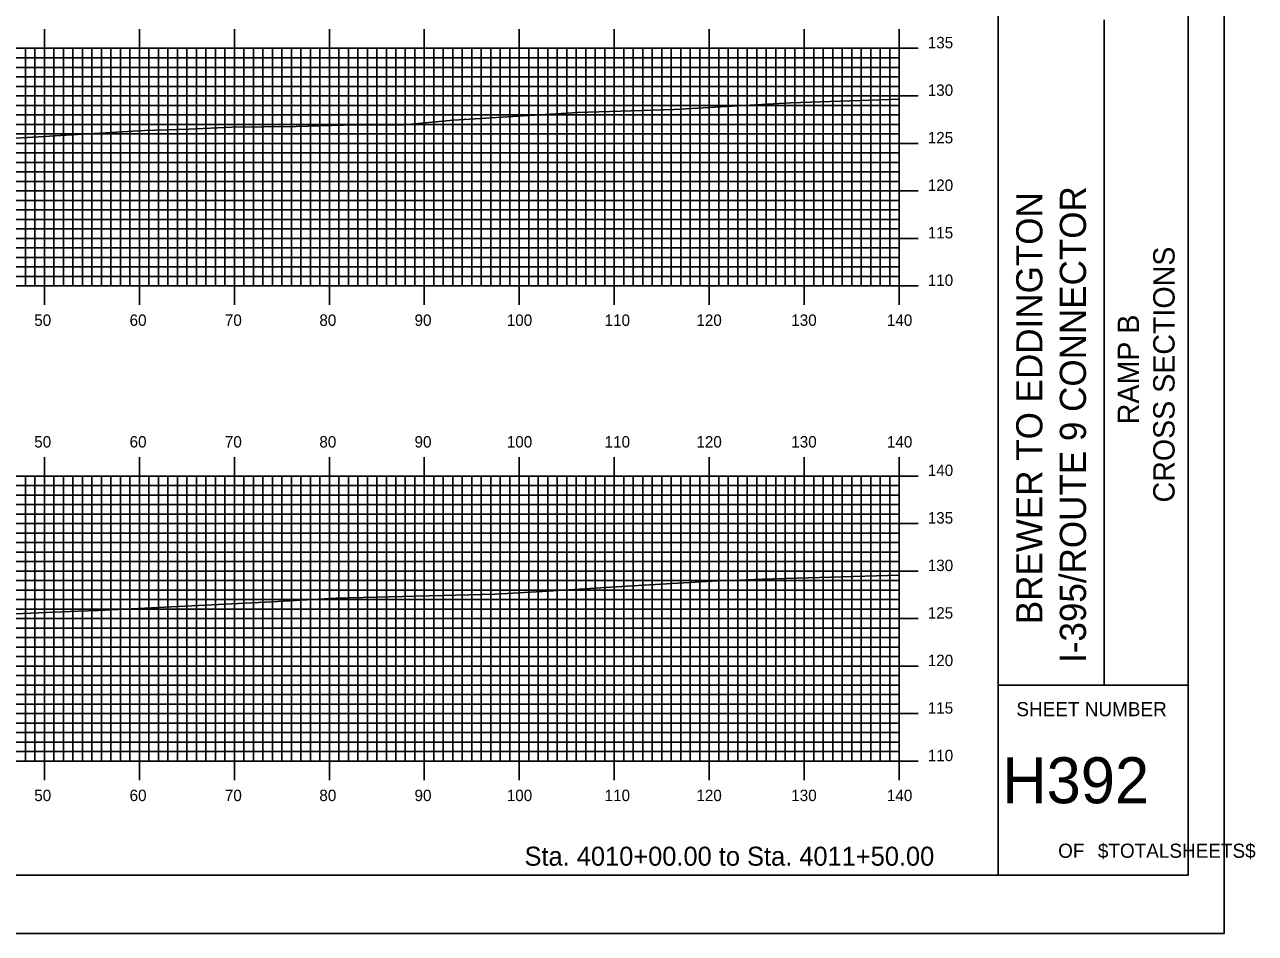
# Model space of a CAD drawing. Extents: x 852540 to 852884, y 364661 to 364881.
# Drawn here: x 852754.2 to 852883.8, y 364661.3 to 364756.9 of the extents above; entities that cross this region are included whole.
import ezdxf

# ---------------------------------------------------------------- set-up
doc = ezdxf.new("R2010")
doc.units = 0
for name, color, linetype in [('BORDER', 7, 'Continuous'), ('H_V ANNOTATION', 7, 'Continuous'), ('MAJOR', 7, 'Continuous'), ('MINOR', 7, 'Continuous'), ('PLOT BOUNDARY', 7, 'Continuous'), ('S_Roadway_Centerline', 7, 'Continuous')]:
    doc.layers.add(name, color=color, linetype=linetype)

msp = doc.modelspace()

# ---------------------------------------------------------------- linework, layer by layer
at = {"layer": 'BORDER'}
for p, q in [((852856.67, 364667.37), (852856.67, 364877.37)), ((852867.85, 364687.38), (852867.85, 364757.38)), ((852856.67, 364687.38), (852876.67, 364687.38))]:
    msp.add_line(p, q, dxfattribs=at)
msp.add_lwpolyline([(852556.67, 364667.37), (852876.67, 364667.37), (852876.67, 364877.37), (852556.67, 364877.37)], close=True, dxfattribs=at)
at = {"layer": 'MAJOR'}
for p, q in [((852756.27, 364756.37), (852756.27, 364754.37)), ((852766.27, 364756.37), (852766.27, 364754.37)), ((852776.27, 364756.37), (852776.27, 364754.37)), ((852786.27, 364756.37), (852786.27, 364754.37)), ((852796.27, 364756.37), (852796.27, 364754.37)), ((852806.27, 364756.37), (852806.27, 364754.37)), ((852816.27, 364756.37), (852816.27, 364754.37)), ((852826.27, 364756.37), (852826.27, 364754.37)), ((852836.27, 364756.37), (852836.27, 364754.37)), ((852846.27, 364756.37), (852846.27, 364754.37)), ((852566.27, 364754.37), (852846.27, 364754.37)), ((852566.27, 364754.37), (852846.27, 364754.37)), ((852756.27, 364729.37), (852756.27, 364754.37)), ((852766.27, 364729.37), (852766.27, 364754.37)), ((852776.27, 364729.37), (852776.27, 364754.37)), ((852786.27, 364729.37), (852786.27, 364754.37)), ((852796.27, 364729.37), (852796.27, 364754.37)), ((852806.27, 364729.37), (852806.27, 364754.37)), ((852816.27, 364729.37), (852816.27, 364754.37)), ((852826.27, 364729.37), (852826.27, 364754.37)), ((852836.27, 364729.37), (852836.27, 364754.37)), ((852848.27, 364754.37), (852844.26, 364754.37)), ((852846.27, 364729.37), (852846.27, 364754.37)), ((852846.27, 364729.37), (852846.27, 364754.37)), ((852566.27, 364749.37), (852846.27, 364749.37)), ((852848.27, 364749.37), (852844.26, 364749.37)), ((852566.27, 364744.37), (852846.27, 364744.37)), ((852848.27, 364744.37), (852844.26, 364744.37)), ((852566.27, 364739.37), (852846.27, 364739.37)), ((852848.27, 364739.37), (852844.26, 364739.37)), ((852566.27, 364734.37), (852846.27, 364734.37)), ((852848.27, 364734.37), (852844.26, 364734.37)), ((852566.27, 364729.37), (852846.27, 364729.37)), ((852566.27, 364729.37), (852846.27, 364729.37)), ((852756.27, 364727.37), (852756.27, 364729.37)), ((852766.27, 364727.37), (852766.27, 364729.37)), ((852776.27, 364727.37), (852776.27, 364729.37)), ((852786.27, 364727.37), (852786.27, 364729.37)), ((852796.27, 364727.37), (852796.27, 364729.37)), ((852806.27, 364727.37), (852806.27, 364729.37)), ((852816.27, 364727.37), (852816.27, 364729.37)), ((852826.27, 364727.37), (852826.27, 364729.37)), ((852836.27, 364727.37), (852836.27, 364729.37)), ((852848.27, 364729.37), (852844.26, 364729.37)), ((852846.27, 364727.37), (852846.27, 364729.37)), ((852756.27, 364711.37), (852756.27, 364709.37)), ((852766.27, 364711.37), (852766.27, 364709.37)), ((852776.27, 364711.37), (852776.27, 364709.37)), ((852786.27, 364711.37), (852786.27, 364709.37)), ((852796.27, 364711.37), (852796.27, 364709.37)), ((852806.27, 364711.37), (852806.27, 364709.37)), ((852816.27, 364711.37), (852816.27, 364709.37)), ((852826.27, 364711.37), (852826.27, 364709.37)), ((852836.27, 364711.37), (852836.27, 364709.37)), ((852846.27, 364711.37), (852846.27, 364709.37)), ((852566.27, 364709.37), (852846.27, 364709.37)), ((852566.27, 364709.37), (852846.27, 364709.37)), ((852756.27, 364679.37), (852756.27, 364709.37)), ((852766.27, 364679.37), (852766.27, 364709.37)), ((852776.27, 364679.37), (852776.27, 364709.37)), ((852786.27, 364679.37), (852786.27, 364709.37)), ((852796.27, 364679.37), (852796.27, 364709.37)), ((852806.27, 364679.37), (852806.27, 364709.37)), ((852816.27, 364679.37), (852816.27, 364709.37)), ((852826.27, 364679.37), (852826.27, 364709.37)), ((852836.27, 364679.37), (852836.27, 364709.37)), ((852848.27, 364709.37), (852844.26, 364709.37)), ((852846.27, 364679.37), (852846.27, 364709.37)), ((852846.27, 364679.37), (852846.27, 364709.37)), ((852566.27, 364704.37), (852846.27, 364704.37)), ((852848.27, 364704.37), (852844.26, 364704.37)), ((852566.27, 364699.37), (852846.27, 364699.37)), ((852848.27, 364699.37), (852844.26, 364699.37)), ((852566.27, 364694.37), (852846.27, 364694.37)), ((852848.27, 364694.37), (852844.26, 364694.37)), ((852566.27, 364689.37), (852846.27, 364689.37)), ((852848.27, 364689.37), (852844.26, 364689.37)), ((852566.27, 364684.37), (852846.27, 364684.37)), ((852848.27, 364684.37), (852844.26, 364684.37)), ((852566.27, 364679.37), (852846.27, 364679.37)), ((852566.27, 364679.37), (852846.27, 364679.37)), ((852756.27, 364677.37), (852756.27, 364679.37)), ((852766.27, 364677.37), (852766.27, 364679.37)), ((852776.27, 364677.37), (852776.27, 364679.37)), ((852786.27, 364677.37), (852786.27, 364679.37)), ((852796.27, 364677.37), (852796.27, 364679.37)), ((852806.27, 364677.37), (852806.27, 364679.37)), ((852816.27, 364677.37), (852816.27, 364679.37)), ((852826.27, 364677.37), (852826.27, 364679.37)), ((852836.27, 364677.37), (852836.27, 364679.37)), ((852848.27, 364679.37), (852844.26, 364679.37)), ((852846.27, 364677.37), (852846.27, 364679.37))]:
    msp.add_line(p, q, dxfattribs=at)
at = {"layer": 'MINOR'}
for p, q in [((852754.27, 364729.37), (852754.27, 364754.37)), ((852755.27, 364729.37), (852755.27, 364754.37)), ((852757.27, 364729.37), (852757.27, 364754.37)), ((852758.27, 364729.37), (852758.27, 364754.37)), ((852759.27, 364729.37), (852759.27, 364754.37)), ((852760.27, 364729.37), (852760.27, 364754.37)), ((852761.27, 364729.37), (852761.27, 364754.37)), ((852762.27, 364729.37), (852762.27, 364754.37)), ((852763.27, 364729.37), (852763.27, 364754.37)), ((852764.27, 364729.37), (852764.27, 364754.37)), ((852765.27, 364729.37), (852765.27, 364754.37)), ((852767.27, 364729.37), (852767.27, 364754.37)), ((852768.27, 364729.37), (852768.27, 364754.37)), ((852769.27, 364729.37), (852769.27, 364754.37)), ((852770.27, 364729.37), (852770.27, 364754.37)), ((852771.27, 364729.37), (852771.27, 364754.37)), ((852772.27, 364729.37), (852772.27, 364754.37)), ((852773.27, 364729.37), (852773.27, 364754.37)), ((852774.27, 364729.37), (852774.27, 364754.37)), ((852775.27, 364729.37), (852775.27, 364754.37)), ((852777.27, 364729.37), (852777.27, 364754.37)), ((852778.27, 364729.37), (852778.27, 364754.37)), ((852779.27, 364729.37), (852779.27, 364754.37)), ((852780.27, 364729.37), (852780.27, 364754.37)), ((852781.27, 364729.37), (852781.27, 364754.37)), ((852782.27, 364729.37), (852782.27, 364754.37)), ((852783.27, 364729.37), (852783.27, 364754.37)), ((852784.27, 364729.37), (852784.27, 364754.37)), ((852785.27, 364729.37), (852785.27, 364754.37)), ((852787.27, 364729.37), (852787.27, 364754.37)), ((852788.27, 364729.37), (852788.27, 364754.37)), ((852789.27, 364729.37), (852789.27, 364754.37)), ((852790.27, 364729.37), (852790.27, 364754.37)), ((852791.27, 364729.37), (852791.27, 364754.37)), ((852792.27, 364729.37), (852792.27, 364754.37)), ((852793.27, 364729.37), (852793.27, 364754.37)), ((852794.27, 364729.37), (852794.27, 364754.37)), ((852795.27, 364729.37), (852795.27, 364754.37)), ((852797.27, 364729.37), (852797.27, 364754.37)), ((852798.27, 364729.37), (852798.27, 364754.37)), ((852799.27, 364729.37), (852799.27, 364754.37)), ((852800.27, 364729.37), (852800.27, 364754.37)), ((852801.27, 364729.37), (852801.27, 364754.37)), ((852802.27, 364729.37), (852802.27, 364754.37)), ((852803.27, 364729.37), (852803.27, 364754.37)), ((852804.27, 364729.37), (852804.27, 364754.37)), ((852805.27, 364729.37), (852805.27, 364754.37)), ((852807.27, 364729.37), (852807.27, 364754.37)), ((852808.27, 364729.37), (852808.27, 364754.37)), ((852809.27, 364729.37), (852809.27, 364754.37)), ((852810.27, 364729.37), (852810.27, 364754.37)), ((852811.27, 364729.37), (852811.27, 364754.37)), ((852812.27, 364729.37), (852812.27, 364754.37)), ((852813.27, 364729.37), (852813.27, 364754.37)), ((852814.27, 364729.37), (852814.27, 364754.37)), ((852815.27, 364729.37), (852815.27, 364754.37)), ((852817.27, 364729.37), (852817.27, 364754.37)), ((852818.27, 364729.37), (852818.27, 364754.37)), ((852819.27, 364729.37), (852819.27, 364754.37)), ((852820.27, 364729.37), (852820.27, 364754.37)), ((852821.27, 364729.37), (852821.27, 364754.37)), ((852822.27, 364729.37), (852822.27, 364754.37)), ((852823.27, 364729.37), (852823.27, 364754.37)), ((852824.27, 364729.37), (852824.27, 364754.37)), ((852825.27, 364729.37), (852825.27, 364754.37)), ((852827.27, 364729.37), (852827.27, 364754.37)), ((852828.27, 364729.37), (852828.27, 364754.37)), ((852829.27, 364729.37), (852829.27, 364754.37)), ((852830.27, 364729.37), (852830.27, 364754.37)), ((852831.27, 364729.37), (852831.27, 364754.37)), ((852832.27, 364729.37), (852832.27, 364754.37)), ((852833.27, 364729.37), (852833.27, 364754.37)), ((852834.27, 364729.37), (852834.27, 364754.37)), ((852835.27, 364729.37), (852835.27, 364754.37)), ((852837.27, 364729.37), (852837.27, 364754.37)), ((852838.27, 364729.37), (852838.27, 364754.37)), ((852839.27, 364729.37), (852839.27, 364754.37)), ((852840.27, 364729.37), (852840.27, 364754.37)), ((852841.27, 364729.37), (852841.27, 364754.37)), ((852842.27, 364729.37), (852842.27, 364754.37)), ((852843.27, 364729.37), (852843.27, 364754.37)), ((852844.27, 364729.37), (852844.27, 364754.37)), ((852845.27, 364729.37), (852845.27, 364754.37)), ((852566.27, 364753.37), (852846.27, 364753.37)), ((852566.27, 364752.37), (852846.27, 364752.37)), ((852846.27, 364753.37), (852844.26, 364753.37)), ((852846.27, 364752.37), (852844.26, 364752.37)), ((852566.27, 364751.37), (852846.27, 364751.37)), ((852846.27, 364751.37), (852844.26, 364751.37)), ((852566.27, 364750.37), (852846.27, 364750.37)), ((852846.27, 364750.37), (852844.26, 364750.37)), ((852566.27, 364748.37), (852846.27, 364748.37)), ((852846.27, 364748.37), (852844.26, 364748.37)), ((852566.27, 364747.37), (852846.27, 364747.37)), ((852846.27, 364747.37), (852844.26, 364747.37)), ((852566.27, 364746.37), (852846.27, 364746.37)), ((852846.27, 364746.37), (852844.26, 364746.37)), ((852566.27, 364745.37), (852846.27, 364745.37)), ((852846.27, 364745.37), (852844.26, 364745.37)), ((852566.27, 364743.37), (852846.27, 364743.37)), ((852846.27, 364743.37), (852844.26, 364743.37)), ((852566.27, 364742.37), (852846.27, 364742.37)), ((852846.27, 364742.37), (852844.26, 364742.37)), ((852566.27, 364741.37), (852846.27, 364741.37)), ((852846.27, 364741.37), (852844.26, 364741.37)), ((852566.27, 364740.37), (852846.27, 364740.37)), ((852846.27, 364740.37), (852844.26, 364740.37)), ((852566.27, 364738.37), (852846.27, 364738.37)), ((852846.27, 364738.37), (852844.26, 364738.37)), ((852566.27, 364737.37), (852846.27, 364737.37)), ((852846.27, 364737.37), (852844.26, 364737.37)), ((852566.27, 364736.37), (852846.27, 364736.37)), ((852566.27, 364735.37), (852846.27, 364735.37)), ((852846.27, 364736.37), (852844.26, 364736.37)), ((852846.27, 364735.37), (852844.26, 364735.37)), ((852566.27, 364733.37), (852846.27, 364733.37)), ((852846.27, 364733.37), (852844.26, 364733.37)), ((852566.27, 364732.37), (852846.27, 364732.37)), ((852566.27, 364731.37), (852846.27, 364731.37)), ((852846.27, 364732.37), (852844.26, 364732.37)), ((852846.27, 364731.37), (852844.26, 364731.37)), ((852566.27, 364730.37), (852846.27, 364730.37)), ((852846.27, 364730.37), (852844.26, 364730.37)), ((852754.27, 364679.37), (852754.27, 364709.37)), ((852755.27, 364679.37), (852755.27, 364709.37)), ((852757.27, 364679.37), (852757.27, 364709.37)), ((852758.27, 364679.37), (852758.27, 364709.37)), ((852759.27, 364679.37), (852759.27, 364709.37)), ((852760.27, 364679.37), (852760.27, 364709.37)), ((852761.27, 364679.37), (852761.27, 364709.37)), ((852762.27, 364679.37), (852762.27, 364709.37)), ((852763.27, 364679.37), (852763.27, 364709.37)), ((852764.27, 364679.37), (852764.27, 364709.37)), ((852765.27, 364679.37), (852765.27, 364709.37)), ((852767.27, 364679.37), (852767.27, 364709.37)), ((852768.27, 364679.37), (852768.27, 364709.37)), ((852769.27, 364679.37), (852769.27, 364709.37)), ((852770.27, 364679.37), (852770.27, 364709.37)), ((852771.27, 364679.37), (852771.27, 364709.37)), ((852772.27, 364679.37), (852772.27, 364709.37)), ((852773.27, 364679.37), (852773.27, 364709.37)), ((852774.27, 364679.37), (852774.27, 364709.37)), ((852775.27, 364679.37), (852775.27, 364709.37)), ((852777.27, 364679.37), (852777.27, 364709.37)), ((852778.27, 364679.37), (852778.27, 364709.37)), ((852779.27, 364679.37), (852779.27, 364709.37)), ((852780.27, 364679.37), (852780.27, 364709.37)), ((852781.27, 364679.37), (852781.27, 364709.37)), ((852782.27, 364679.37), (852782.27, 364709.37)), ((852783.27, 364679.37), (852783.27, 364709.37)), ((852784.27, 364679.37), (852784.27, 364709.37)), ((852785.27, 364679.37), (852785.27, 364709.37)), ((852787.27, 364679.37), (852787.27, 364709.37)), ((852788.27, 364679.37), (852788.27, 364709.37)), ((852789.27, 364679.37), (852789.27, 364709.37)), ((852790.27, 364679.37), (852790.27, 364709.37)), ((852791.27, 364679.37), (852791.27, 364709.37)), ((852792.27, 364679.37), (852792.27, 364709.37)), ((852793.27, 364679.37), (852793.27, 364709.37)), ((852794.27, 364679.37), (852794.27, 364709.37)), ((852795.27, 364679.37), (852795.27, 364709.37)), ((852797.27, 364679.37), (852797.27, 364709.37)), ((852798.27, 364679.37), (852798.27, 364709.37)), ((852799.27, 364679.37), (852799.27, 364709.37)), ((852800.27, 364679.37), (852800.27, 364709.37)), ((852801.27, 364679.37), (852801.27, 364709.37)), ((852802.27, 364679.37), (852802.27, 364709.37)), ((852803.27, 364679.37), (852803.27, 364709.37)), ((852804.27, 364679.37), (852804.27, 364709.37)), ((852805.27, 364679.37), (852805.27, 364709.37)), ((852807.27, 364679.37), (852807.27, 364709.37)), ((852808.27, 364679.37), (852808.27, 364709.37)), ((852809.27, 364679.37), (852809.27, 364709.37)), ((852810.27, 364679.37), (852810.27, 364709.37)), ((852811.27, 364679.37), (852811.27, 364709.37)), ((852812.27, 364679.37), (852812.27, 364709.37)), ((852813.27, 364679.37), (852813.27, 364709.37)), ((852814.27, 364679.37), (852814.27, 364709.37)), ((852815.27, 364679.37), (852815.27, 364709.37)), ((852817.27, 364679.37), (852817.27, 364709.37)), ((852818.27, 364679.37), (852818.27, 364709.37)), ((852819.27, 364679.37), (852819.27, 364709.37)), ((852820.27, 364679.37), (852820.27, 364709.37)), ((852821.27, 364679.37), (852821.27, 364709.37)), ((852822.27, 364679.37), (852822.27, 364709.37)), ((852823.27, 364679.37), (852823.27, 364709.37)), ((852824.27, 364679.37), (852824.27, 364709.37)), ((852825.27, 364679.37), (852825.27, 364709.37)), ((852827.27, 364679.37), (852827.27, 364709.37)), ((852828.27, 364679.37), (852828.27, 364709.37)), ((852829.27, 364679.37), (852829.27, 364709.37)), ((852830.27, 364679.37), (852830.27, 364709.37)), ((852831.27, 364679.37), (852831.27, 364709.37)), ((852832.27, 364679.37), (852832.27, 364709.37)), ((852833.27, 364679.37), (852833.27, 364709.37)), ((852834.27, 364679.37), (852834.27, 364709.37)), ((852835.27, 364679.37), (852835.27, 364709.37)), ((852837.27, 364679.37), (852837.27, 364709.37)), ((852838.27, 364679.37), (852838.27, 364709.37)), ((852839.27, 364679.37), (852839.27, 364709.37)), ((852840.27, 364679.37), (852840.27, 364709.37)), ((852841.27, 364679.37), (852841.27, 364709.37)), ((852842.27, 364679.37), (852842.27, 364709.37)), ((852843.27, 364679.37), (852843.27, 364709.37)), ((852844.27, 364679.37), (852844.27, 364709.37)), ((852845.27, 364679.37), (852845.27, 364709.37)), ((852566.27, 364708.37), (852846.27, 364708.37)), ((852846.27, 364708.37), (852844.26, 364708.37)), ((852566.27, 364707.37), (852846.27, 364707.37)), ((852846.27, 364707.37), (852844.26, 364707.37)), ((852566.27, 364706.37), (852846.27, 364706.37)), ((852846.27, 364706.37), (852844.26, 364706.37)), ((852566.27, 364705.37), (852846.27, 364705.37)), ((852846.27, 364705.37), (852844.26, 364705.37)), ((852566.27, 364703.37), (852846.27, 364703.37)), ((852846.27, 364703.37), (852844.26, 364703.37)), ((852566.27, 364702.37), (852846.27, 364702.37)), ((852846.27, 364702.37), (852844.26, 364702.37)), ((852566.27, 364701.37), (852846.27, 364701.37)), ((852566.27, 364700.37), (852846.27, 364700.37)), ((852846.27, 364701.37), (852844.26, 364701.37)), ((852846.27, 364700.37), (852844.26, 364700.37)), ((852566.27, 364698.37), (852846.27, 364698.37)), ((852846.27, 364698.37), (852844.26, 364698.37)), ((852566.27, 364697.37), (852846.27, 364697.37)), ((852846.27, 364697.37), (852844.26, 364697.37)), ((852566.27, 364696.37), (852846.27, 364696.37)), ((852566.27, 364695.37), (852846.27, 364695.37)), ((852846.27, 364696.37), (852844.26, 364696.37)), ((852846.27, 364695.37), (852844.26, 364695.37)), ((852566.27, 364693.37), (852846.27, 364693.37)), ((852846.27, 364693.37), (852844.26, 364693.37)), ((852566.27, 364692.37), (852846.27, 364692.37)), ((852566.27, 364691.37), (852846.27, 364691.37)), ((852846.27, 364692.37), (852844.26, 364692.37)), ((852846.27, 364691.37), (852844.26, 364691.37)), ((852566.27, 364690.37), (852846.27, 364690.37)), ((852846.27, 364690.37), (852844.26, 364690.37)), ((852566.27, 364688.37), (852846.27, 364688.37)), ((852566.27, 364687.37), (852846.27, 364687.37)), ((852846.27, 364688.37), (852844.26, 364688.37)), ((852846.27, 364687.37), (852844.26, 364687.37)), ((852566.27, 364686.37), (852846.27, 364686.37)), ((852846.27, 364686.37), (852844.26, 364686.37)), ((852566.27, 364685.37), (852846.27, 364685.37)), ((852846.27, 364685.37), (852844.26, 364685.37)), ((852566.27, 364683.37), (852846.27, 364683.37)), ((852566.27, 364682.37), (852846.27, 364682.37)), ((852846.27, 364683.37), (852844.26, 364683.37)), ((852846.27, 364682.37), (852844.26, 364682.37)), ((852566.27, 364681.37), (852846.27, 364681.37)), ((852846.27, 364681.37), (852844.26, 364681.37)), ((852566.27, 364680.37), (852846.27, 364680.37)), ((852846.27, 364680.37), (852844.26, 364680.37))]:
    msp.add_line(p, q, dxfattribs=at)
at = {"layer": 'PLOT BOUNDARY'}
msp.add_lwpolyline([(852540.48, 364661.25), (852880.48, 364661.25), (852880.48, 364881.25), (852540.48, 364881.25)], close=True, dxfattribs=at)
at = {"layer": 'S_Roadway_Centerline'}
for points in [[(852747.98, 364744.6), (852766.82, 364745.71), (852771.49, 364745.85), (852776, 364746.08), (852782.79, 364746.13), (852788.99, 364746.32), (852794.11, 364746.33), (852799.34, 364746.8), (852812.41, 364747.62), (852822.58, 364747.93), (852834.86, 364748.63), (852846.27, 364749.02)], [(852740.34, 364694.32), (852757.27, 364695.05), (852759.86, 364695.15), (852761.93, 364695.22), (852780.23, 364696.14), (852786.98, 364696.51), (852803.77, 364696.94), (852809.26, 364697.25), (852818.18, 364697.82), (852827.16, 364698.33), (852829.49, 364698.4), (852831.86, 364698.52), (852846.27, 364698.94)]]:
    msp.add_lwpolyline(points, dxfattribs=at)

# ---------------------------------------------------------------- texts
at = {"layer": 'BORDER'}
for s, height, p in [('I-395/ROUTE 9 CONNECTOR', 2.7557, (852865.93, 364689.7)), ('BREWER TO EDDINGTON', 2.7557, (852861.34, 364693.78)), ('CROSS SECTIONS', 2.25, (852875.26, 364706.59)), ('RAMP B', 2.25, (852871.51, 364714.82))]:
    msp.add_text(s, height=height, rotation=90, dxfattribs=at).set_placement(p)
for s, height, p in [('SHEET NUMBER', 1.4905, (852858.6, 364684.1)), ('H392', 4.839, (852857.11, 364674.94)), ('OF', 1.491, (852863, 364669.2)), ('$TOTALSHEETS$', 1.4905, (852867.18, 364669.2))]:
    msp.add_text(s, height=height, dxfattribs=at).set_placement(p)
at = {"layer": 'H_V ANNOTATION'}
for s, height, p in [('135', 1.2, (852849.27, 364754.37)), ('130', 1.2, (852849.27, 364749.37)), ('125', 1.2, (852849.27, 364744.37)), ('120', 1.2, (852849.27, 364739.37)), ('115', 1.2, (852849.27, 364734.37)), ('110', 1.2, (852849.27, 364729.37)), ('50', 1.2, (852755.2, 364725.17)), ('60', 1.2, (852765.24, 364725.17)), ('70', 1.2, (852775.27, 364725.17)), ('80', 1.2, (852785.22, 364725.17)), ('90', 1.2, (852795.24, 364725.17)), ('100', 1.2, (852804.95, 364725.17)), ('110', 1.2, (852815.25, 364725.17)), ('120', 1.2, (852824.91, 364725.17)), ('130', 1.2, (852834.9, 364725.17)), ('140', 1.2, (852844.97, 364725.17)), ('50', 1.2, (852755.2, 364712.37)), ('60', 1.2, (852765.24, 364712.37)), ('70', 1.2, (852775.27, 364712.37)), ('80', 1.2, (852785.22, 364712.37)), ('90', 1.2, (852795.24, 364712.37)), ('100', 1.2, (852804.95, 364712.37)), ('110', 1.2, (852815.25, 364712.37)), ('120', 1.2, (852824.91, 364712.37)), ('130', 1.2, (852834.9, 364712.37)), ('140', 1.2, (852844.97, 364712.37)), ('140', 1.2, (852849.27, 364709.37)), ('135', 1.2, (852849.27, 364704.37)), ('130', 1.2, (852849.27, 364699.37)), ('125', 1.2, (852849.27, 364694.37)), ('120', 1.2, (852849.27, 364689.37)), ('115', 1.2, (852849.27, 364684.37)), ('110', 1.2, (852849.27, 364679.37)), ('50', 1.2, (852755.2, 364675.17)), ('60', 1.2, (852765.24, 364675.17)), ('70', 1.2, (852775.27, 364675.17)), ('80', 1.2, (852785.22, 364675.17)), ('90', 1.2, (852795.24, 364675.17)), ('100', 1.2, (852804.95, 364675.17)), ('110', 1.2, (852815.25, 364675.17)), ('120', 1.2, (852824.91, 364675.17)), ('130', 1.2, (852834.9, 364675.17)), ('140', 1.2, (852844.97, 364675.17)), ('Sta. 4010+00.00 to Sta. 4011+50.00', 2.0004, (852806.82, 364668.37))]:
    msp.add_text(s, height=height, dxfattribs=at).set_placement(p)

doc.saveas('drawing.dxf')
